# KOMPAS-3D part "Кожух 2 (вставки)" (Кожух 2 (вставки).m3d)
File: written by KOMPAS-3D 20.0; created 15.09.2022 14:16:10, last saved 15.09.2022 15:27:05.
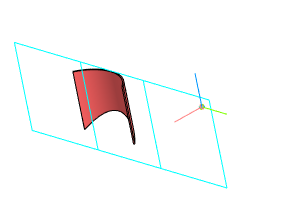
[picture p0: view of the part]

Document properties: Полное имя файла: D:\YAKOVLEV\ПРОЕКТЫ\ДЦ-2. ДП-7 Газопровод Окожушивание\ПРОБА Соединение труб. Окожушивание\Кожух 2 (вставки).m3d

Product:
- Part/product: Кожух 2 (вставки)
    Материал: Сталь 45  ГОСТ 1050-2013 (density 7810 kg/m3)
    Масса: 74.3647

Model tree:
1. Эскиз:1  (with: Смещенная плоскость:1, Обечайка:1)  (labels: Кожух 2 (вставки))
2. Обечайка:1  (labels: Кожух 1 (трубы); Кожух 2 (вставки))
     Расстояние 1 = 823.908
3. Сгиб(1) - Обечайка:1
     Радиус сгиба = 530; Коэффициент = 0.5; Величина сгиба = 10; Зазор = 0.01; Угол = 180; Параметр U, % = 11; Длина = 366.31
4. Касательная плоскость:1  (with: Обечайка:1)
5. Разогнуть:1  (with: Обечайка:1)
6. Смещенная плоскость:1  (with: Обечайка:1)
     Расстояние = 0.1
7. Эскиз:3  (with: Обечайка:1)
8. Вырез в листовом теле:3
     Глубина выреза = 100
9. Элемент выдавливания:1
     Расстояние 2 = 20
10. Эскиз:4  (with: Обечайка:1, Вырез в листовом теле:3)
11. Вырез в листовом теле:4
     Глубина выреза = 100
12. Эскиз:5  (with: Обечайка:1)
13. Вырез в листовом теле:5
     Глубина выреза = 10
14. Согнуть:1  (with: Обечайка:1)
15. Развертка  (labels: Сталь 45  ГОСТ 1050-2013)

Expressions: v172*2
Referenced files in D:\YAKOVLEV\ПРОЕКТЫ\ДЦ-2. ДП-7 Газопровод Окожушивание\ПРОБА Соединение труб. Окожушивание\: Соединение труб. Окожушивание -2.a3d
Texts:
  Соединение труб. Окожушивание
